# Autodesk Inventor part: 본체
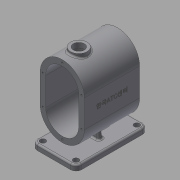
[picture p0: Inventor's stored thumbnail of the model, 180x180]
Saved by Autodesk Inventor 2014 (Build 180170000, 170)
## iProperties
Created: 2016-12
Part Number: 본체
Material: Aluminum 6061
Document SubType Name: Modeling
Designer: mduedu
Density: 2.71 g/cm^3
Appearance: Default
Mass: 1146.21 g
Surface Area: 978.821 cm^2
Volume: 422.955 cm^3
Author: mduedu
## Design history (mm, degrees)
sketch "스케치1"
  geometry: L1 (40, -25)-(40, 25); L2 (-40, 25)-(-40, -25); L3 (-40, -25)-(40, 25); L4 (40, -25)-(-40, 25); L5 (0, 25)-(0, -25); A1 r 40 centre (0, 25) between (40, 25) and (-40, 25); A2 r 40 centre (0, -25) between (-40, -25) and (40, -25); 1 further point
  constraints: 10 end point, 4 point on circle, 3 tangent, 2 centre point, 2 midpoint, 2 parallel, 1 vertical
  dimensions: "d0" = 130 dimension on A2 A1; "d2" = 80 distance between parallel lines of L1 L2
extrude "돌출1" new body sketch "스케치1" stored distance "d3" = 100; taper "d4" = 0 deg
feature "쉘1" dims "d5" = 10
sketch "스케치2"
  geometry: L1 (-75, 65)-(-85, 65); L2 (-85, 65)-(-85, -65); L3 (-85, -65)-(-75, -65); L4 (-75, -65)-(-75, 65); 2 further points
  constraints: 8 end point, 2 parallel, 1 horizontal, 1 horizontal alignment, 1 midpoint, 1 perpendicular
  dimensions: "d6" = 85 distance from line of L2 point (0, 0); "d7" = 130 distance of L1.end L2.end; "d8" = 10 distance of L2.end L3.end
extrude "돌출2" join sketch "스케치2" stored distance "d9" = 80; taper "d10" = 0 deg
fillet "모깎기1" dims "d11" = 10
sketch "스케치3"
  geometry: L1 (-10, 10)-(-10, 120) reference; L2 (60, 0)-(0, 0) reference; L3 (70, 120)-(70, 10) reference; L4 (0, 130)-(60, 130) reference; A1 r 10 centre (0, 120) between (0, 130) and (-10, 120) reference; A2 r 10 centre (0, 10) between (-10, 10) and (0, 0) reference; A3 r 10 centre (60, 10) between (60, 0) and (70, 10) reference; A4 r 10 centre (60, 120) between (70, 120) and (60, 130) reference; 5 further points
  constraints: 4 coincident
hole "구멍1" sketch "스케치3" at (60, 120), (60, 10), (0, 10), (0, 120) diameter "d12" = 10; stored, may be unused: countersink angle "d16" = 90 deg, drill point angle "d18" = 118 deg; dims "d13" = 6, "d14" = 4, "d15" = 2, "d17" = 8
sketch "스케치5"
  geometry: L1 (34, 35)-(26, 35); L2 (26, 35)-(26, 95); L3 (26, 95)-(34, 95); L4 (34, 95)-(34, 35); L5 (34, 35)-(26, 95); L6 (26, 35)-(34, 95); 1 further point
  constraints: 12 end point, 2 midpoint, 2 parallel, 1 horizontal, 1 perpendicular
  dimensions: "d22" = 8 distance of L2.end L3.end; "d24" = 60 distance of L1.end L2.end
extrude "돌출3" join sketch "스케치5" stored distance "d25" = 80; taper "d26" = 0 deg
feature "면 기울기1" dims angle "d27" = 5 deg
sketch "스케치6"
  geometry: L1 (-30, -75)-(30, -75) reference; L2 (-17.524, -60.957)-(-20, -75); A1 r 40 centre (0, -25) between (-40, -25) and (40, -25) reference; 1 further point
  constraints: 2 end point, 1 point on circle, 1 point on line
  dimensions: "d28" = 20 horizontal distance of A1.centre L2.end; "d29" = 80 deg angle of L2 L1
feature "리브1" sketch "스케치6" dims "d30" = 1, "d31" = 8, "d32" = 0, "d33" = 0, "d34" = 1, "d35" = 1
fillet "모깎기2" dims "d36" = 3
fillet "모깎기3" dims "d37" = 3, "d38" = 3
node "작업 평면1"
sketch "스케치9"
  geometry: 1 further point
sketch "스케치7"
  geometry: L1 (40, 50)-(-40, 50) reference; C1 r 15 at (0, 20); 1 further point
  constraints: 1 centre point, 1 vertical alignment
  dimensions: "d40" = 30 diameter of C1; "d41" = 30 distance from line of C1.centre L1
extrude "돌출4" join sketch "스케치7" stored distance "d42" = 80; taper "d43" = 0 deg
hole "구멍2" diameter "d46" = 20; stored, may be unused: countersink angle "d50" = 90 deg, drill point angle "d52" = 118 deg; dims "d44" = 10, "d45" = 10, "d47" = 6, "d48" = 4, "d49" = 2, "d51" = 8
fillet "모깎기4" dims "d53" = 3
node "작업 평면2"
sketch "스케치8"
  geometry: C1 r 15 at (0, 0) reference; C2 r 15 at (0, 0); 1 further point
  constraints: 1 centre point, 1 coincident
  dimensions: "d55" = 30 diameter of C2
extrude "돌출5" cut sketch "스케치8" stored distance "d56" = 80; taper "d57" = 0 deg
chamfer "모따기1" distance "d58" = 1; stored, may be unused: second distance "d59" = 2, angle "d60" = 45 deg
sketch "스케치10"
  geometry: 2 further points
  constraints: 1 coincident, 1 other
feature "엠보싱1" sketch "스케치10" dims "d0" = 130, "d2" = 80, "d61" = 0.5, "d62" = 0
sketch "스케치11"
  geometry: 1 further point
hole "구멍3" sketch "스케치11" at (0, 60) diameter "d63" = 3.242; stored, may be unused: countersink angle "d67" = 90 deg, drill point angle "d69" = 120 deg; dims "d64" = 8.6, "d65" = 4, "d66" = 2, "d68" = 10.6
sketch "스케치12"
  geometry: 1 further point
hole "구멍5" sketch "스케치12" at (0, 60) diameter "d70" = 3.242; stored, may be unused: countersink angle "d74" = 90 deg, drill point angle "d76" = 120 deg; dims "d71" = 8.6, "d72" = 4, "d73" = 2, "d75" = 10.6
node "솔리드1"
mirror "대칭1"
pattern_linear "직사각형 패턴1"
pattern_linear "직사각형 패턴2"
node "투영된 루프1"
sketch "스케치13"
  geometry: L1 (-40, 25)-(-40, -25) reference; L2 (40, -25)-(40, 25) reference; L3 (35, 25)-(35, -25); L4 (-35, -25)-(-35, 25); A1 r 40 centre (0, 25) between (40, 25) and (-40, 25) reference; A2 r 40 centre (0, -25) between (-40, -25) and (40, -25) reference; A3 r 35 centre (0, 25) between (35, 25) and (-35, 25); A4 r 35 centre (0, -25) between (-35, -25) and (35, -25); 2 further points
  constraints: 5 point on circle, 4 end point, 2 centre point, 3 other
  dimensions: "d77" = 5 distance between parallel lines of L3 L2
sketch "스케치14"
  geometry: L1 (-40, 25)-(-40, -25) reference; L2 (40, -25)-(40, 25) reference; L3 (35, 25)-(35, -25); L4 (-35, -25)-(-35, 25); A1 r 40 centre (0, 25) between (40, 25) and (-40, 25) reference; A2 r 40 centre (0, -25) between (-40, -25) and (40, -25) reference; A3 r 35 centre (0, 25) between (35, 25) and (-35, 25); A4 r 35 centre (0, -25) between (-35, -25) and (35, -25); 2 further points
  constraints: 5 point on circle, 4 end point, 2 centre point, 3 other
  dimensions: "d80" = 5 distance between parallel lines of L2 L3
